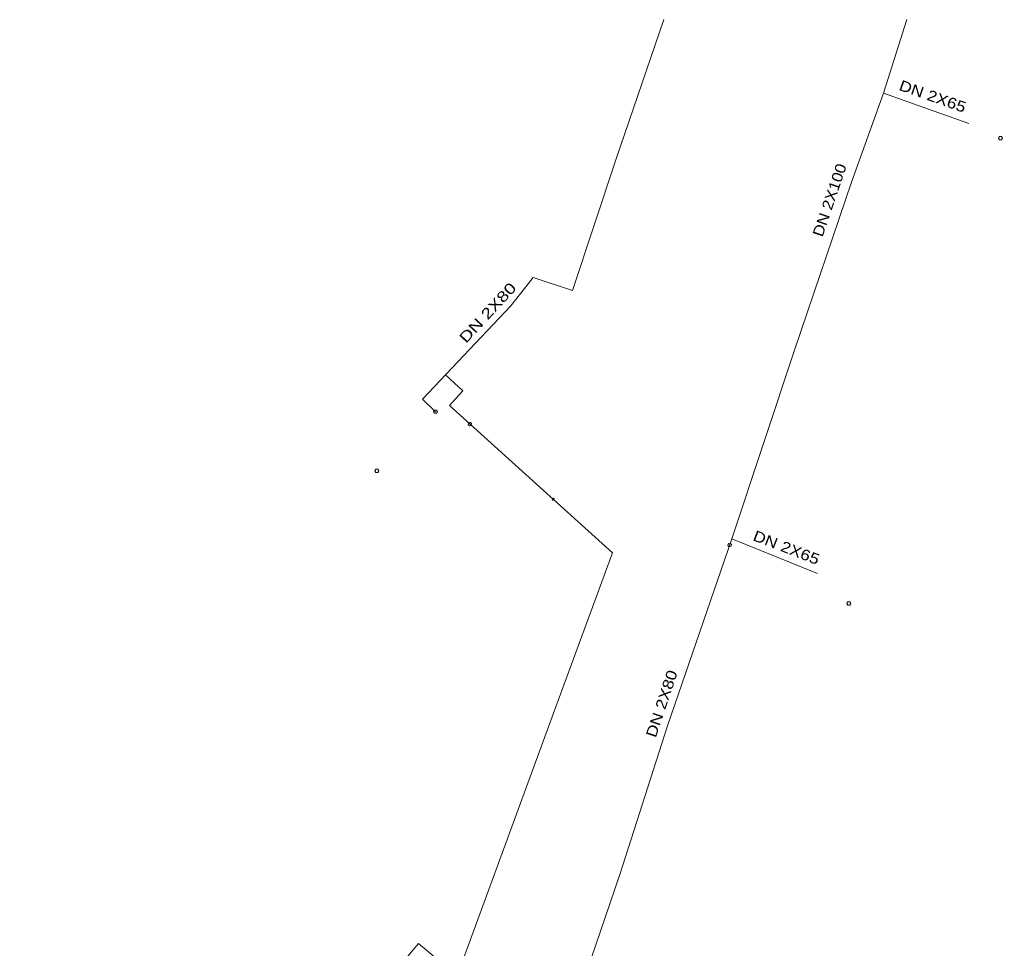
# Model space of a CAD drawing. Extents: x -725606 to -725269, y -977352 to -977136.
# Drawn here: x -725541.3 to -725449.3, y -977223.1 to -977136.2 of the extents above; entities that cross this region are included whole.
import ezdxf
from ezdxf.enums import TextEntityAlignment as Align

# ---------------------------------------------------------------- set-up
doc = ezdxf.new("R2010")
doc.units = 0
doc.header["$LTSCALE"] = 0.2
doc.layers.add('63', color=7, linetype='Continuous', lineweight=13)

msp = doc.modelspace()

# ---------------------------------------------------------------- linework, layer by layer
at = {"layer": '63'}
for points in [[(-725502.41, -977172.9), (-725503.642, -977171.729), (-725495.35, -977163), (-725493.28, -977160.34), (-725489.6, -977161.56), (-725485.52, -977149.33), (-725481.027, -977136.198)], [(-725458.288, -977136.198), (-725460.48, -977143.08), (-725452.49, -977145.92)], [(-725460.48, -977143.08), (-725463.48, -977151.42), (-725468.73, -977166.95), (-725474.68, -977184.79), (-725466.66, -977188.03)], [(-725501.45, -977169.48), (-725499.84, -977170.93), (-725501.11, -977172.33), (-725485.83, -977186.1), (-725491.16, -977200.54), (-725500.38, -977225.7), (-725503.99, -977222.67), (-725520.46, -977242.21), (-725540.4, -977236.86), (-725541.34, -977241.18)], [(-725474.68, -977184.79), (-725480.68, -977202.29), (-725485.17, -977216.21), (-725489.21, -977228.12), (-725480, -977231.01)]]:
    msp.add_lwpolyline(points, dxfattribs=at)
for points in [[(-725449.438, -977147.14), (-725449.348, -977147.29), (-725449.438, -977147.44), (-725449.618, -977147.44), (-725449.708, -977147.29), (-725449.618, -977147.14)], [(-725502.32, -977172.75), (-725502.23, -977172.9), (-725502.32, -977173.05), (-725502.5, -977173.05), (-725502.59, -977172.9), (-725502.5, -977172.75)], [(-725499.368, -977174.095), (-725499.327, -977173.925), (-725499.157, -977173.882), (-725499.029, -977174.009), (-725499.071, -977174.179), (-725499.241, -977174.222)], [(-725507.808, -977178.287), (-725507.718, -977178.437), (-725507.808, -977178.587), (-725507.988, -977178.587), (-725508.078, -977178.437), (-725507.988, -977178.287)], [(-725491.317, -977181.058), (-725491.338, -977181.143), (-725491.423, -977181.164), (-725491.486, -977181.1), (-725491.465, -977181.016), (-725491.38, -977180.994)], [(-725474.765, -977185.509), (-725474.935, -977185.55), (-725475.052, -977185.42), (-725474.998, -977185.248), (-725474.828, -977185.206), (-725474.712, -977185.337)], [(-725463.636, -977190.701), (-725463.546, -977190.851), (-725463.636, -977191.001), (-725463.816, -977191.001), (-725463.906, -977190.851), (-725463.816, -977190.701)]]:
    msp.add_lwpolyline(points, close=True, dxfattribs=at)

# ---------------------------------------------------------------- texts
for s, rotation, width, p in [('DN 2X65', 340.623, 1.2, (-725456.0329, -977143.8418)), ('DN 2X100', 71.219, 1.15, (-725465.0481, -977153.2465)), ('DN 2X80', 47.212, 1.3, (-725497.1564, -977163.9691)), ('DN 2X65', 338.962, 1.2, (-725469.7415, -977186.0803)), ('DN 2X80', 71.562, 1.2, (-725480.7622, -977200.3871))]:
    msp.add_text(s, height=1, rotation=rotation, dxfattribs=dict(at, width=width)).set_placement(p, align=Align.CENTER)

doc.saveas('drawing.dxf')
